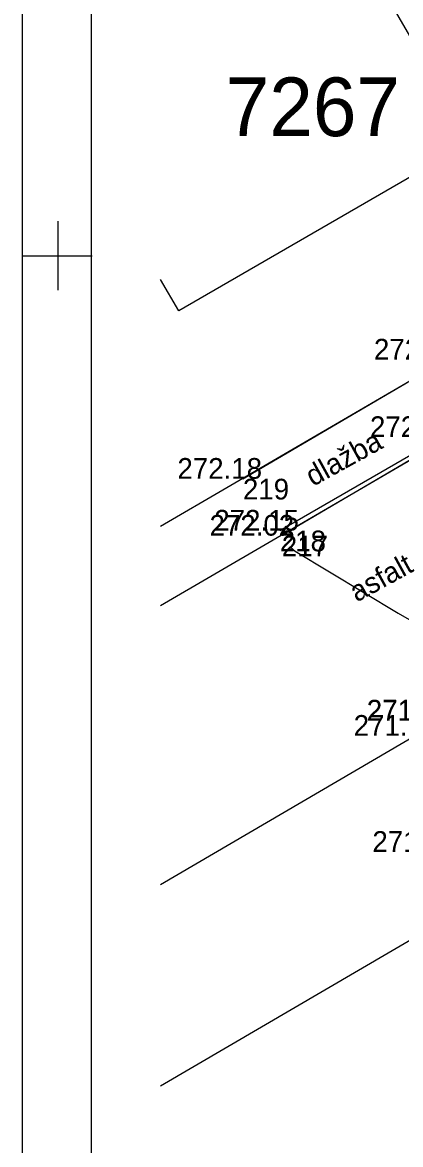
# Model space of a CAD drawing. Extents: x -771260 to -770828, y -1053564 to -1052811.
# Drawn here: x -771251.02 to -771240.06, y -1053175.75 to -1053143.24 of the extents above; entities that cross this region are included whole.
import ezdxf

# ---------------------------------------------------------------- set-up
doc = ezdxf.new("R2010")
doc.units = 0
for name, color, linetype in [('14_8_2023_krizky', 7, 'Continuous'), ('25_3_2019_krizky_JTSK', 7, 'Continuous'), ('25_3_2019_obrubnik', 7, 'Continuous'), ('25_3_2019_oploceni', 7, 'Continuous'), ('25_3_2019_popis_povrchu', 7, 'Continuous'), ('25_3_2019_ram_ggs', 7, 'Continuous'), ('25_3_2019_vrstevnice_interval_po_1m', 7, 'Continuous'), ('25_3_2019_zamereny_bod', 7, 'Continuous'), ('25_3_2019_zamereny_bod_cislo', 7, 'Continuous'), ('25_3_2019_zamereny_bod_vyska', 7, 'Continuous'), ('Default', 7, 'Continuous'), ('DKM_Hranice parcel', 7, 'Continuous'), ('DKM_Parcelní čísla', 7, 'Continuous')]:
    doc.layers.add(name, color=color, linetype=linetype)

# ---------------------------------------------------------------- blocks, each defined once
blk = doc.blocks.new('POINT_DISPLAY')
at = {"layer": 'Default'}
blk.add_line((0, 0), (0, 0), dxfattribs=at)
blk = doc.blocks.new('KRIZEK')
at = {"layer": '25_3_2019_krizky_JTSK'}
for p, q in [((0, 10), (0, -10)), ((-10, 0), (10, 0))]:
    blk.add_line(p, q, dxfattribs=at)

msp = doc.modelspace()

# ---------------------------------------------------------------- linework, layer by layer
at = {"layer": '25_3_2019_obrubnik'}
for p, q in [((-771237.95, -1053154.841), (-771243.502, -1053158.111)), ((-771243.56, -1053157.966), (-771238.871, -1053155.254))]:
    msp.add_line(p, q, dxfattribs=at)
at = {"layer": '25_3_2019_oploceni'}
msp.add_line((-771244.629, -1053156.464), (-771238.746, -1053153.01), dxfattribs=at)
at = {"layer": '25_3_2019_ram_ggs'}
for points in [[(-771251.022, -1053563.673), (-771251.022, -1052969.173), (-770830.522, -1052969.173), (-770830.522, -1053563.673)], [(-771249.022, -1053561.673), (-771249.022, -1052971.173), (-770832.522, -1052971.173), (-770832.522, -1053561.673)]]:
    msp.add_lwpolyline(points, close=True, dxfattribs=at)
at = {"layer": '25_3_2019_vrstevnice_interval_po_1m'}
for points in [[(-771243.254, -1053158.445), (-771243.254, -1053158.445)], [(-771243.254, -1053158.445), (-771243.183, -1053158.504), (-771243.112, -1053158.563), (-771240.128, -1053160.355), (-771239.171, -1053160.907)], [(-771243.112, -1053158.563), (-771243.112, -1053158.563)], [(-771240.128, -1053160.355), (-771240.128, -1053160.355)]]:
    msp.add_lwpolyline(points, dxfattribs=at)
at = {"layer": 'DKM_Hranice parcel'}
for p, q in [((-771231.6, -1053148.85), (-771247.022, -1053157.851)), ((-771233.14, -1053165.96), (-771247.022, -1053174.06))]:
    msp.add_line(p, q, dxfattribs=at)
for points in [[(-771247.022, -1053131.224), (-771238.01, -1053146.7), (-771246.49, -1053151.6)], [(-771246.49, -1053151.6), (-771247.022, -1053150.687)], [(-771227.83, -1053156.67), (-771231.15, -1053150.9), (-771247.022, -1053160.146)], [(-771247.022, -1053168.215), (-771233.82, -1053160.5), (-771229.59, -1053161.44), (-771226.84, -1053159.87)]]:
    msp.add_lwpolyline(points, dxfattribs=at)

# ---------------------------------------------------------------- block references
at = {"layer": '14_8_2023_krizky', "xscale": 0.1, "yscale": 0.10000000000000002}
msp.add_blockref('KRIZEK', (-771250, -1053150), dxfattribs=at)
at = {"layer": '25_3_2019_zamereny_bod', "xscale": 0.1, "yscale": 0.10000000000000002}
for p in [(-771244.629, -1053156.464), (-771243.561, -1053157.966), (-771243.502, -1053158.112)]:
    msp.add_blockref('POINT_DISPLAY', p, dxfattribs=at)

# ---------------------------------------------------------------- texts
at = {"layer": '25_3_2019_popis_povrchu'}
for s, rotation, p in [('dlažba', 28.8427, (-771242.6, -1053156.698)), ('asfalt', 28.6957, (-771241.329, -1053160.051))]:
    msp.add_text(s, height=0.6, rotation=rotation, dxfattribs=at).set_placement(p)
at = {"layer": '25_3_2019_zamereny_bod_cislo'}
for s, p in [('219', (-771244.629, -1053157.064)), ('218', (-771243.561, -1053158.566)), ('217', (-771243.502, -1053158.712))]:
    msp.add_text(s, height=0.6, dxfattribs=at).set_placement(p)
at = {"layer": '25_3_2019_zamereny_bod_vyska'}
for s, p in [('272.67 ', (-771240.83, -1053153.01)), ('272.49 ', (-771240.946, -1053155.255)), ('272.18 ', (-771246.528, -1053156.464)), ('272.02 ', (-771245.598, -1053158.112)), ('272.15 ', (-771245.46, -1053157.966)), ('271.85 ', (-771241.04, -1053163.469)), ('271.85 ', (-771241.036, -1053163.473)), ('271.78 ', (-771241.418, -1053163.911)), ('271.91 ', (-771240.876, -1053167.274))]:
    msp.add_text(s, height=0.6, dxfattribs=at).set_placement(p)
at = {"layer": 'DKM_Parcelní čísla'}
msp.add_text('7267', height=1.7, dxfattribs=at).set_placement((-771245.131, -1053146.537))

doc.saveas('drawing.dxf')
